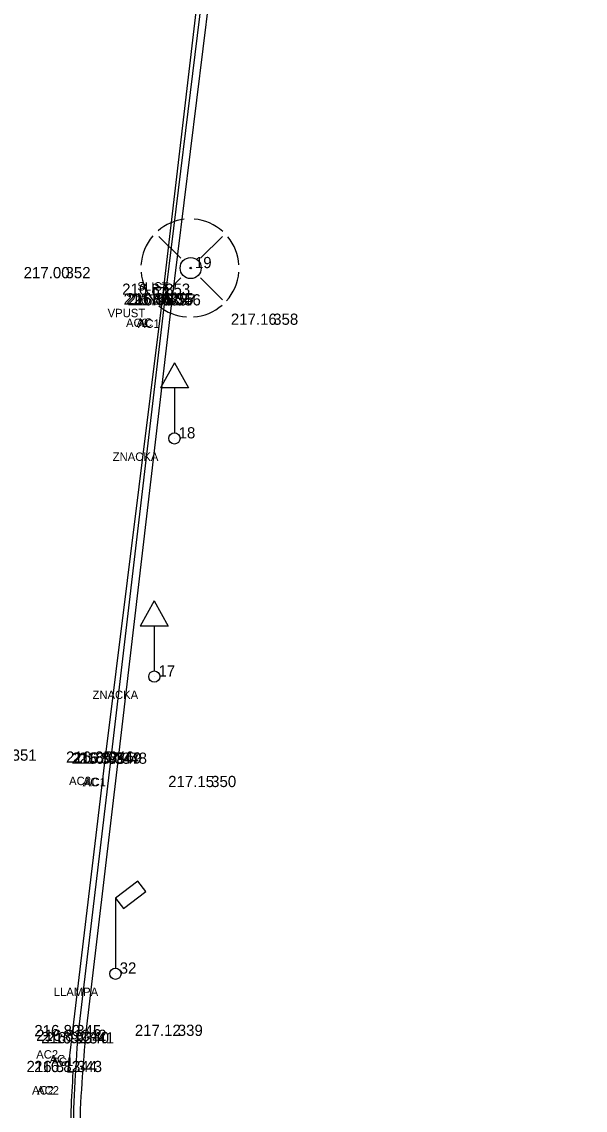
# Model space of a CAD drawing. Extents: x -471047 to -470889, y -1102859 to -1102000.
# Drawn here: x -470987.01 to -470966.93, y -1102709.11 to -1102670.31 of the extents above; entities that cross this region are included whole.
import ezdxf

# ---------------------------------------------------------------- set-up
doc = ezdxf.new("R2010")
doc.units = 0
for name, color, linetype in [('Vrstva 1', 7, 'Continuous'), ('Vrstva 16', 7, 'Continuous'), ('Vrstva 19', 7, 'Continuous'), ('Vrstva 23', 7, 'Continuous'), ('Vrstva 25', 7, 'Continuous'), ('Vrstva 34', 7, 'Continuous'), ('Vrstva 35', 7, 'Continuous'), ('Vrstva 36', 7, 'Continuous'), ('Vrstva 38', 7, 'Continuous'), ('Vrstva 5', 7, 'Continuous'), ('Vrstva 7', 7, 'Continuous'), ('Vrstva 8', 7, 'Continuous')]:
    doc.layers.add(name, color=color, linetype=linetype)

msp = doc.modelspace()

# ---------------------------------------------------------------- linework, layer by layer
at = {"layer": 'Vrstva 1'}
for points in [[(-471040.344, -1102858.385), (-471031.676, -1102846.187), (-471026.357, -1102838.629), (-471023.212, -1102833.975), (-471019.21, -1102827.465), (-471016.861, -1102823.272), (-471013.099, -1102815.912), (-471010.824, -1102810.955), (-471007.329, -1102802.292), (-471005.34, -1102796.515), (-471002.842, -1102787.838), (-471001.3, -1102780.997), (-471000.19, -1102774.713), (-470999.247, -1102768.204), (-470998.794, -1102764.784), (-470997.199, -1102751.812), (-470994.899, -1102732.807), (-470992.551, -1102713.262), (-470990.326, -1102694.887), (-470988.122, -1102676.57), (-470985.812, -1102657.305), (-470983.537, -1102638.407), (-470981.386, -1102620.622), (-470979.843, -1102608.014), (-470976.377, -1102579.253), (-470972.945, -1102550.69), (-470970.475, -1102530.206), (-470967.905, -1102508.801), (-470965.053, -1102485.131), (-470962.734, -1102465.9), (-470960.173, -1102444.812), (-470957.795, -1102425.103), (-470954.965, -1102401.839), (-470953.834, -1102392.574), (-470952.33, -1102379.985), (-470950.744, -1102366.853), (-470948.978, -1102352.106), (-470947.037, -1102335.844), (-470944.949, -1102318.462), (-470944.013, -1102310.745), (-470942.39, -1102297.267), (-470939.519, -1102273.45), (-470937.593, -1102257.43), (-470936.064, -1102244.81), (-470934.114, -1102228.634), (-470931.621, -1102207.856), (-470929.536, -1102190.857), (-470926.572, -1102166.31), (-470924.91, -1102152.663), (-470923.413, -1102140.333), (-470921.923, -1102127.669), (-470921.155, -1102120.084), (-470920.446, -1102109.574), (-470919.912, -1102099.137), (-470919.63, -1102088.981), (-470919.523, -1102081.193), (-470919.563, -1102070.395), (-470919.714, -1102064.236), (-470920.134, -1102054.704), (-470920.462, -1102047.615), (-470920.599, -1102044.52), (-470920.743, -1102041.873), (-470921.125, -1102034.455), (-470921.774, -1102030.337), (-470922.418, -1102027.787), (-470923.734, -1102023.93), (-470924.872, -1102021.434), (-470926.752, -1102018.182), (-470927.953, -1102016.45), (-470929.616, -1102014.424), (-470932.252, -1102011.756), (-470935.111, -1102009.425), (-470938.391, -1102007.371), (-470942.651, -1102005.401)], [(-471041.328, -1102857.18), (-471032.144, -1102844.242), (-471027.583, -1102837.763), (-471024.388, -1102833.028), (-471020.451, -1102826.6), (-471018.089, -1102822.378), (-471014.542, -1102815.445), (-471012.233, -1102810.418), (-471009.247, -1102803.108), (-471006.795, -1102796.098), (-471004.315, -1102787.532), (-471002.782, -1102780.723), (-471001.674, -1102774.458), (-471000.75, -1102768.095), (-471000.28, -1102764.601), (-470998.692, -1102751.741), (-470996.378, -1102732.635), (-470994.028, -1102713.058), (-470991.808, -1102694.749), (-470989.616, -1102676.447), (-470987.284, -1102657.013), (-470985.031, -1102638.272), (-470982.87, -1102620.431), (-470981.334, -1102607.933), (-470977.881, -1102579.263), (-470974.429, -1102550.492), (-470971.964, -1102530.054), (-470969.391, -1102508.607), (-470966.54, -1102484.984), (-470964.231, -1102465.853), (-470961.679, -1102444.752), (-470959.304, -1102425.078), (-470956.455, -1102401.634), (-470955.339, -1102392.489), (-470953.812, -1102379.71), (-470952.249, -1102366.808), (-470950.479, -1102352.023), (-470948.536, -1102335.868), (-470946.426, -1102318.233), (-470945.493, -1102310.531), (-470943.864, -1102297.013), (-470940.984, -1102273.071), (-470939.078, -1102257.195), (-470937.559, -1102244.684), (-470935.592, -1102228.353), (-470933.101, -1102207.653), (-470931.011, -1102190.57), (-470928.046, -1102166.021), (-470926.409, -1102152.578), (-470924.898, -1102140.121), (-470923.427, -1102127.544), (-470922.647, -1102119.826), (-470921.919, -1102109.229), (-470921.42, -1102099.134), (-470921.127, -1102089.016), (-470921.023, -1102081.453), (-470921.061, -1102070.468), (-470921.209, -1102064.314), (-470921.666, -1102053.966), (-470922.156, -1102043.345), (-470922.299, -1102039.934), (-470922.637, -1102034.36), (-470923.091, -1102031.241), (-470923.847, -1102028.247), (-470925.083, -1102024.594), (-470926.222, -1102022.086), (-470928.04, -1102018.943), (-470929.138, -1102017.357), (-470930.929, -1102015.175), (-470933.062, -1102013.049), (-470936.379, -1102010.368), (-470939.169, -1102008.662), (-470942.899, -1102006.906), (-470945.661, -1102005.908)], [(-471043.557, -1102855.955), (-471035.129, -1102844.026), (-471029.872, -1102836.499), (-471026.577, -1102831.578), (-471022.675, -1102825.415), (-471020.123, -1102821.053), (-471016.667, -1102814.59), (-471014.208, -1102809.45), (-471011.177, -1102802.451), (-471008.55, -1102795.333), (-471006.082, -1102787.209), (-471004.464, -1102780.376), (-471003.265, -1102774.167), (-471002.327, -1102767.948), (-471001.636, -1102762.527), (-471000.297, -1102751.605), (-470997.959, -1102732.524), (-470995.602, -1102712.802), (-470993.412, -1102694.623), (-470991.21, -1102676.17), (-470988.891, -1102656.857), (-470986.625, -1102638.083), (-470984.455, -1102620.195), (-470982.936, -1102607.733), (-470979.497, -1102579.223), (-470976.023, -1102550.279), (-470973.554, -1102529.822), (-470970.991, -1102508.497), (-470968.146, -1102484.787), (-470965.835, -1102465.72), (-470963.284, -1102444.529), (-470960.91, -1102424.942), (-470958.043, -1102401.343), (-470956.946, -1102392.356), (-470955.396, -1102379.408), (-470953.851, -1102366.636), (-470952.049, -1102351.733), (-470950.124, -1102335.611), (-470948.034, -1102318.083), (-470947.094, -1102310.328), (-470945.421, -1102296.51), (-470942.58, -1102272.848), (-470940.675, -1102256.948), (-470939.176, -1102244.526), (-470937.187, -1102228.174), (-470934.708, -1102207.467), (-470932.621, -1102190.433), (-470929.634, -1102165.778), (-470928.004, -1102152.415), (-470926.45, -1102139.595), (-470925.003, -1102127.418), (-470924.249, -1102119.695), (-470923.515, -1102109.093), (-470923.018, -1102099.069), (-470922.711, -1102088.911), (-470922.643, -1102081.356), (-470922.797, -1102070.414), (-470923.018, -1102064.454), (-470923.52, -1102053.203), (-470923.823, -1102047.529), (-470924.123, -1102041.506), (-470924.462, -1102037.486), (-470924.934, -1102031.904), (-470925.664, -1102028.672), (-470926.771, -1102025.506), (-470927.959, -1102022.914), (-470929.674, -1102020.028), (-470930.76, -1102018.498), (-470932.447, -1102016.478), (-470935.215, -1102013.816), (-470937.644, -1102011.98), (-470940.381, -1102010.371), (-470943.968, -1102008.669), (-470947.145, -1102007.524), (-470950.874, -1102006.74)], [(-471044.756, -1102855.056), (-471036.376, -1102843.177), (-471031.167, -1102835.741), (-471027.859, -1102830.8), (-471023.934, -1102824.593), (-471021.43, -1102820.312), (-471018.011, -1102813.91), (-471015.536, -1102808.75), (-471012.578, -1102801.897), (-471009.95, -1102794.77), (-471007.561, -1102786.914), (-471005.936, -1102780.074), (-471004.727, -1102773.818), (-471003.828, -1102767.827), (-471003.121, -1102762.345), (-471001.787, -1102751.467), (-470999.446, -1102732.348), (-470997.073, -1102712.539), (-470994.902, -1102694.521), (-470992.696, -1102676.023), (-470990.376, -1102656.68), (-470988.131, -1102638.071), (-470985.947, -1102620.018), (-470984.417, -1102607.512), (-470980.993, -1102579.08), (-470977.514, -1102550.137), (-470975.048, -1102529.649), (-470972.488, -1102508.37), (-470969.618, -1102484.508), (-470967.34, -1102465.669), (-470964.767, -1102444.39), (-470962.402, -1102424.781), (-470959.534, -1102401.193), (-470958.432, -1102392.151), (-470956.883, -1102379.208), (-470955.335, -1102366.424), (-470953.535, -1102351.506), (-470951.606, -1102335.399), (-470949.519, -1102317.94), (-470948.575, -1102310.159), (-470946.889, -1102296.144), (-470944.056, -1102272.618), (-470942.139, -1102256.659), (-470940.657, -1102244.341), (-470938.638, -1102227.749), (-470936.19, -1102207.298), (-470934.102, -1102190.255), (-470931.124, -1102165.639), (-470929.492, -1102152.254), (-470927.915, -1102139.252), (-470926.46, -1102127.103), (-470925.74, -1102119.604), (-470925.012, -1102108.913), (-470924.523, -1102099.054), (-470924.217, -1102088.866), (-470924.148, -1102081.334), (-470924.301, -1102070.391), (-470924.518, -1102064.43), (-470924.97, -1102054.435), (-470925.588, -1102041.569), (-470925.963, -1102035.313), (-470926.405, -1102032.225), (-470927.078, -1102029.198), (-470928.123, -1102026.148), (-470929.318, -1102023.558), (-470930.84, -1102020.97), (-470931.868, -1102019.515), (-470933.443, -1102017.605), (-470936.26, -1102014.885), (-470938.429, -1102013.255), (-470941.213, -1102011.639), (-470944.847, -1102009.927), (-470947.723, -1102008.912), (-470951.444, -1102008.161), (-470954.511, -1102007.931), (-470957.895, -1102008.041)]]:
    msp.add_spline(points, degree=3, dxfattribs=at)
at = {"layer": 'Vrstva 16'}
for p, q in [((-470981.346, -1102678.731), (-470982.122, -1102677.956)), ((-470980.636, -1102678.731), (-470979.862, -1102677.956)), ((-470981.346, -1102679.441), (-470982.122, -1102680.216)), ((-470980.636, -1102679.441), (-470979.862, -1102680.216))]:
    msp.add_line(p, q, dxfattribs=at)
for radius in [0.375, 0.025, 0.025]:
    msp.add_circle((-470980.991, -1102679.086), radius, dxfattribs=at)
for start, end in [(96.7144, 130.447), (48.1897, 84.9117), (139.23, 176.4602), (3.8615, 39.6013), (184.9408, 222.2827), (318.1086, 355.0481), (230.4703, 265.8356), (274.1732, 310.7861)]:
    msp.add_arc((-470981.017, -1102679.086), 1.75, start, end, dxfattribs=at)
at = {"layer": 'Vrstva 19'}
for p, q in [((-470981.569, -1102682.46), (-470982.069, -1102683.36)), ((-470981.569, -1102682.46), (-470981.069, -1102683.36)), ((-470981.069, -1102683.36), (-470982.069, -1102683.36)), ((-470981.569, -1102683.36), (-470981.569, -1102684.96)), ((-470982.288, -1102690.951), (-470982.788, -1102691.851)), ((-470982.288, -1102690.951), (-470981.788, -1102691.851)), ((-470981.788, -1102691.851), (-470982.788, -1102691.851)), ((-470982.288, -1102691.851), (-470982.288, -1102693.451))]:
    msp.add_line(p, q, dxfattribs=at)
for centre in [(-470981.569, -1102685.16), (-470982.288, -1102693.651)]:
    msp.add_circle(centre, 0.2, dxfattribs=at)
at = {"layer": 'Vrstva 23'}
for p, q in [((-470982.878, -1102700.939), (-470983.673, -1102701.544)), ((-470982.588, -1102701.316), (-470982.878, -1102700.939)), ((-470983.386, -1102701.922), (-470982.588, -1102701.316)), ((-470983.673, -1102701.544), (-470983.673, -1102704.044)), ((-470983.673, -1102701.544), (-470983.386, -1102701.922))]:
    msp.add_line(p, q, dxfattribs=at)
msp.add_circle((-470983.673, -1102704.244), 0.2, dxfattribs=at)
at = {"layer": 'Vrstva 25'}
for p, q in [((-470982.304, -1102679.795), (-470982.304, -1102680.295)), ((-470981.804, -1102679.795), (-470982.304, -1102679.795)), ((-470982.304, -1102680.045), (-470981.804, -1102680.045)), ((-470981.804, -1102680.295), (-470981.804, -1102679.795)), ((-470982.304, -1102680.295), (-470981.804, -1102680.295))]:
    msp.add_line(p, q, dxfattribs=at)
at = {"layer": 'Vrstva 34'}
for p, q in [((-470980.99, -1102679.09), (-470980.99, -1102679.09)), ((-470985.6, -1102679.45), (-470985.6, -1102679.45)), ((-470982.05, -1102680.04), (-470982.05, -1102680.04)), ((-470982.02, -1102680.39), (-470982.02, -1102680.39)), ((-470981.93, -1102680.38), (-470981.93, -1102680.38)), ((-470981.86, -1102680.42), (-470981.86, -1102680.42)), ((-470981.67, -1102680.42), (-470981.67, -1102680.42)), ((-470978.2, -1102681.11), (-470978.2, -1102681.11)), ((-470981.57, -1102685.16), (-470981.57, -1102685.16)), ((-470982.29, -1102693.65), (-470982.29, -1102693.65)), ((-470984.05, -1102696.72), (-470984.05, -1102696.72)), ((-470983.79, -1102696.75), (-470983.79, -1102696.75)), ((-470983.85, -1102696.76), (-470983.85, -1102696.76)), ((-470983.59, -1102696.76), (-470983.59, -1102696.76)), ((-470980.41, -1102697.59), (-470980.41, -1102697.59)), ((-470983.67, -1102704.24), (-470983.67, -1102704.24)), ((-470985.22, -1102706.47), (-470985.22, -1102706.47)), ((-470985.03, -1102706.64), (-470985.03, -1102706.64)), ((-470984.94, -1102706.72), (-470984.94, -1102706.72)), ((-470984.76, -1102706.73), (-470984.76, -1102706.73)), ((-470981.6, -1102706.46), (-470981.6, -1102706.46)), ((-470985.37, -1102707.75), (-470985.37, -1102707.75)), ((-470985.19, -1102707.75), (-470985.19, -1102707.75))]:
    msp.add_line(p, q, dxfattribs=at)
at = {"layer": 'Vrstva 5'}
for p, q in [((-470982.018, -1102680.393), (-470979.92, -1102662.44)), ((-470984.046, -1102696.718), (-470982.018, -1102680.393)), ((-470985.219, -1102706.47), (-470984.046, -1102696.718)), ((-470985.366, -1102707.753), (-470985.219, -1102706.47)), ((-470985.188, -1102707.748), (-470985.366, -1102707.753))]:
    msp.add_line(p, q, dxfattribs=at)
msp.add_spline([(-470985.188, -1102707.748), (-470985.298, -1102710.513), (-470985.121, -1102714.009), (-470984.319, -1102718.787), (-470983.462, -1102721.691), (-470982.346, -1102724.837), (-470980.868, -1102728.306), (-470979.814, -1102730.112), (-470978.15, -1102732.217), (-470976.904, -1102733.436), (-470974.289, -1102735.317)], degree=3, dxfattribs=at)
at = {"layer": 'Vrstva 7'}
for p, q in [((-470981.674, -1102680.42), (-470979.463, -1102662.478)), ((-470983.585, -1102696.758), (-470981.674, -1102680.42)), ((-470984.764, -1102706.728), (-470983.585, -1102696.758))]:
    msp.add_line(p, q, dxfattribs=at)
msp.add_spline([(-470984.764, -1102706.728), (-470984.956, -1102710.493), (-470984.752, -1102713.964)], degree=3, dxfattribs=at)
at = {"layer": 'Vrstva 8'}
for p, q in [((-470981.927, -1102680.379), (-470979.724, -1102662.441)), ((-470983.854, -1102696.764), (-470981.927, -1102680.379)), ((-470985.029, -1102706.638), (-470983.854, -1102696.764))]:
    msp.add_line(p, q, dxfattribs=at)
msp.add_spline([(-470985.029, -1102706.638), (-470985.194, -1102710.505), (-470985.025, -1102713.978), (-470984.214, -1102718.758), (-470983.352, -1102721.645), (-470982.297, -1102724.793), (-470980.745, -1102728.214), (-470979.687, -1102730.074), (-470978.076, -1102732.15), (-470976.791, -1102733.373), (-470974.19, -1102735.241)], degree=3, dxfattribs=at)

# ---------------------------------------------------------------- texts
at = {"layer": 'Vrstva 35'}
for s, p in [('SLIST', (-470982.89, -1102679.89)), ('VPUST', (-470983.95, -1102680.84)), ('AC2', (-470983.295, -1102681.19)), ('AC', (-470982.919, -1102681.18)), ('AC1', (-470982.87, -1102681.22)), ('ZNACKA', (-470983.77, -1102685.96)), ('ZNACKA', (-470984.49, -1102694.45)), ('AC2', (-470985.325, -1102697.52)), ('AC', (-470984.839, -1102697.56)), ('AC1', (-470984.79, -1102697.56)), ('LLAMPA', (-470985.87, -1102705.04)), ('AC2', (-470986.495, -1102707.27)), ('AC', (-470986.019, -1102707.44)), ('AC1', (-470985.96, -1102707.53)), ('AC2', (-470986.645, -1102708.55)), ('AC2', (-470986.465, -1102708.55))]:
    msp.add_text(s, height=0.3, dxfattribs=at).set_placement(p)
at = {"layer": 'Vrstva 36'}
for s, p in [(' 19', (-470980.99, -1102679.09)), (' 352', (-470985.6, -1102679.45)), (' 353', (-470982.05, -1102680.04)), (' 354', (-470982.02, -1102680.39)), (' 355', (-470981.93, -1102680.38)), (' 357', (-470981.86, -1102680.42)), (' 356', (-470981.67, -1102680.42)), (' 358', (-470978.2, -1102681.11)), (' 18', (-470981.57, -1102685.16)), (' 17', (-470982.29, -1102693.65)), (' 351', (-470987.52, -1102696.65)), (' 346', (-470984.05, -1102696.72)), (' 347', (-470983.85, -1102696.76)), (' 349', (-470983.79, -1102696.75)), (' 348', (-470983.59, -1102696.76)), (' 350', (-470980.41, -1102697.59)), (' 32', (-470983.67, -1102704.24)), (' 345', (-470985.22, -1102706.47)), (' 339', (-470981.6, -1102706.46)), (' 342', (-470985.03, -1102706.64)), (' 340', (-470984.94, -1102706.72)), (' 341', (-470984.76, -1102706.73)), (' 344', (-470985.37, -1102707.75)), (' 343', (-470985.19, -1102707.75))]:
    msp.add_text(s, height=0.4, dxfattribs=at).set_placement(p)
at = {"layer": 'Vrstva 38'}
for s, p in [('217.00 ', (-470986.943, -1102679.45)), ('216.87 ', (-470983.433, -1102680.04)), ('216.86 ', (-470983.38, -1102680.39)), ('216.86 ', (-470983.29, -1102680.38)), ('216.99 ', (-470983.244, -1102680.42)), ('217.02 ', (-470983.051, -1102680.42)), ('217.16 ', (-470979.56, -1102681.11)), ('216.85 ', (-470985.434, -1102696.72)), ('216.87 ', (-470985.233, -1102696.76)), ('216.97 ', (-470985.173, -1102696.75)), ('216.98 ', (-470984.974, -1102696.76)), ('217.15 ', (-470981.794, -1102697.59)), ('216.80 ', (-470986.563, -1102706.47)), ('217.12 ', (-470982.981, -1102706.46)), ('216.81 ', (-470986.5, -1102706.64)), ('216.92 ', (-470986.321, -1102706.72)), ('216.93 ', (-470986.143, -1102706.73)), ('216.81 ', (-470986.84, -1102707.75)), ('216.82 ', (-470986.571, -1102707.75))]:
    msp.add_text(s, height=0.4, dxfattribs=at).set_placement(p)

doc.saveas('drawing.dxf')
